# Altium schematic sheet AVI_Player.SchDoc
size A
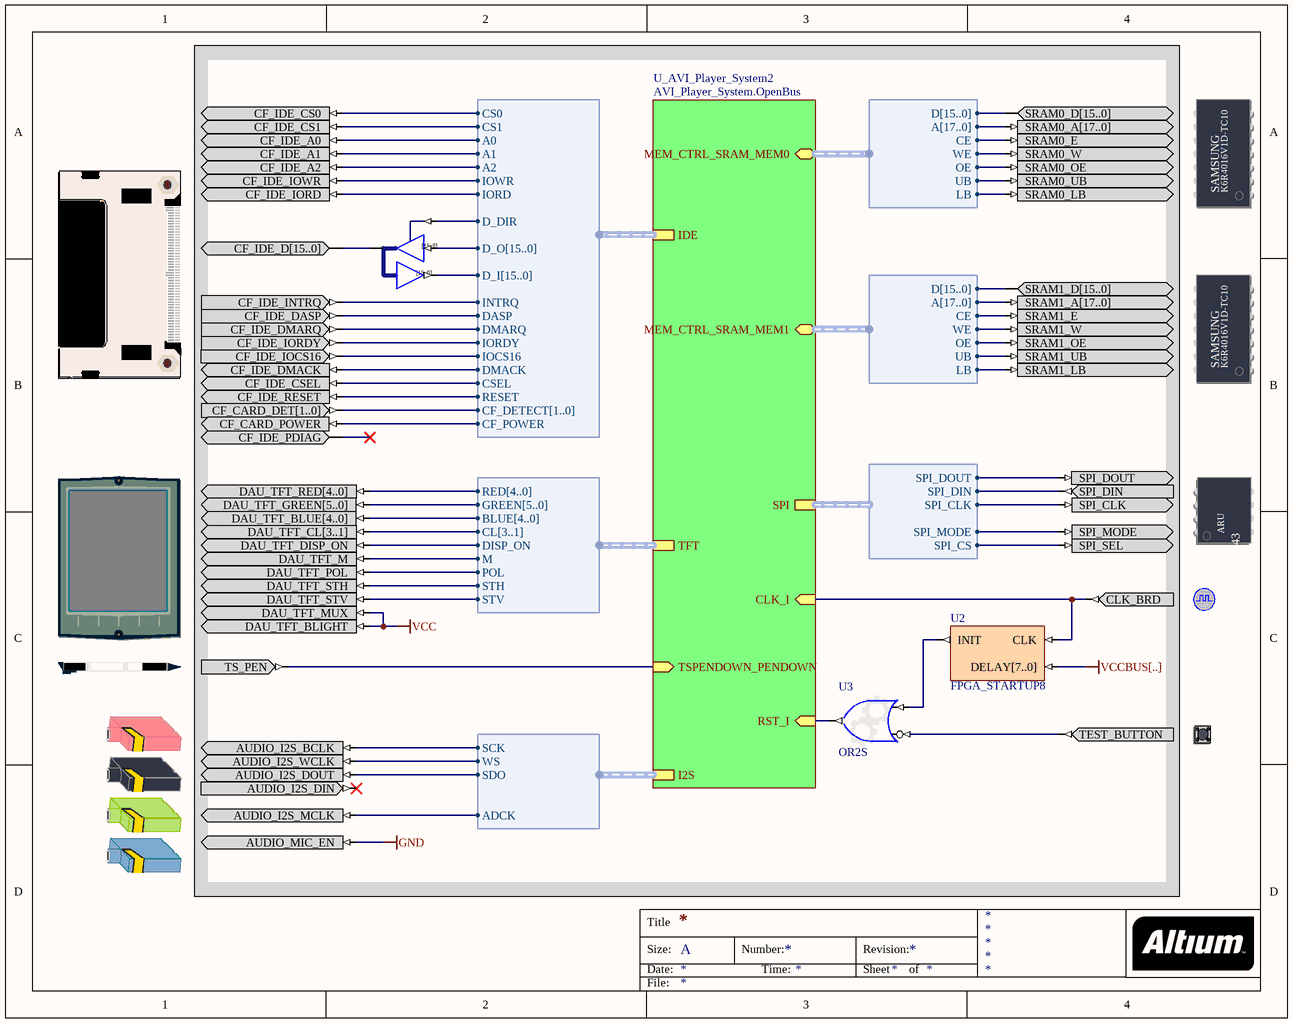
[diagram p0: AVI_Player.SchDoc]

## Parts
(Parts that share a designator on the sheet are numbered #1, #2 ... from top to bottom, then left to right.)
?#1  COMPACT_FLASH  (value not drawn)
?#2  SRAM_DAUGHTER0  (value not drawn)
?#3  SRAM_DAUGHTER1  (value not drawn)
?#4  TFT_LCD  (value not drawn)
?#5  TOUCH_SCREEN_DIGITIZER  (value not drawn)
?#6  CLOCK_BOARD  (value not drawn)
?#7  TOUCHSCREEN_PEN_DOWN  (value not drawn)
?#8  TEST_BUTTON  (value not drawn)
?#9  AUDIO_CODEC  (value not drawn)
U1  IOBUF16B  (value not drawn)
U2  FPGA_STARTUP8
U3  OR2S

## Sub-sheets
U_AVI_Player_System2 = AVI_Player_System.OpenBus: I2S (harness I2S_W_TX), SPI (harness SPI_W_NB), TSPENDOWN_PENDOWN (in), TFT (harness VGA32_TFT), IDE (harness WB_IDE), RST_I (in), CLK_I (in), MEM_CTRL_SRAM_MEM0 (harness WB_MEM_CTRL_SRAM16_A18), MEM_CTRL_SRAM_MEM1 (harness WB_MEM_CTRL_SRAM16_A18)

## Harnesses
WB_IDE: CS0, CS1, A0, A1, A2, IOWR, IORD, D_DIR, D_O[15..0], D_I[15..0], INTRQ, DASP, DMARQ, IORDY, IOCS16, DMACK, CSEL, RESET, CF_DETECT[1..0], CF_POWER
VGA32_TFT: RED[4..0], GREEN[5..0], BLUE[4..0], CL[3..1], DISP_ON, M, POL, STH, STV
SPI_W_NB: SPI_DOUT, SPI_DIN, SPI_CLK, SPI_MODE, SPI_CS
I2S_W_TX: SCK, WS, SDO, ADCK
WB_MEM_CTRL_SRAM16_A18: D[15..0], A[17..0], CE, WE, OE, UB, LB

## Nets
GND: ?#9.AUDIO_MIC_EN
VCC: ?#4.DAU_TFT_BLIGHT ?#4.DAU_TFT_MUX
Net?#1_CF_CARD_POWER: ?#1.CF_CARD_POWER ; sheet U_AVI_Player_System2/IDE.CF_POWER
Net?#1_CF_IDE_A0: ?#1.CF_IDE_A0 ; sheet U_AVI_Player_System2/IDE.A0
Net?#1_CF_IDE_A1: ?#1.CF_IDE_A1 ; sheet U_AVI_Player_System2/IDE.A1
Net?#1_CF_IDE_A2: ?#1.CF_IDE_A2 ; sheet U_AVI_Player_System2/IDE.A2
Net?#1_CF_IDE_CS0: ?#1.CF_IDE_CS0 ; sheet U_AVI_Player_System2/IDE.CS0
Net?#1_CF_IDE_CS1: ?#1.CF_IDE_CS1 ; sheet U_AVI_Player_System2/IDE.CS1
Net?#1_CF_IDE_CSEL: ?#1.CF_IDE_CSEL ; sheet U_AVI_Player_System2/IDE.CSEL
Net?#1_CF_IDE_DASP: ?#1.CF_IDE_DASP ; sheet U_AVI_Player_System2/IDE.DASP
Net?#1_CF_IDE_DMACK: ?#1.CF_IDE_DMACK ; sheet U_AVI_Player_System2/IDE.DMACK
Net?#1_CF_IDE_DMARQ: ?#1.CF_IDE_DMARQ ; sheet U_AVI_Player_System2/IDE.DMARQ
Net?#1_CF_IDE_INTRQ: ?#1.CF_IDE_INTRQ ; sheet U_AVI_Player_System2/IDE.INTRQ
Net?#1_CF_IDE_IOCS16: ?#1.CF_IDE_IOCS16 ; sheet U_AVI_Player_System2/IDE.IOCS16
Net?#1_CF_IDE_IORD: ?#1.CF_IDE_IORD ; sheet U_AVI_Player_System2/IDE.IORD
Net?#1_CF_IDE_IORDY: ?#1.CF_IDE_IORDY ; sheet U_AVI_Player_System2/IDE.IORDY
Net?#1_CF_IDE_IOWR: ?#1.CF_IDE_IOWR ; sheet U_AVI_Player_System2/IDE.IOWR
Net?#1_CF_IDE_RESET: ?#1.CF_IDE_RESET ; sheet U_AVI_Player_System2/IDE.RESET
Net?#2_SRAM0_E: ?#2.SRAM0_E ; sheet U_AVI_Player_System2/MEM_CTRL_SRAM_MEM0.CE
Net?#2_SRAM0_LB: ?#2.SRAM0_LB ; sheet U_AVI_Player_System2/MEM_CTRL_SRAM_MEM0.LB
Net?#2_SRAM0_OE: ?#2.SRAM0_OE ; sheet U_AVI_Player_System2/MEM_CTRL_SRAM_MEM0.OE
Net?#2_SRAM0_UB: ?#2.SRAM0_UB ; sheet U_AVI_Player_System2/MEM_CTRL_SRAM_MEM0.UB
Net?#2_SRAM0_W: ?#2.SRAM0_W ; sheet U_AVI_Player_System2/MEM_CTRL_SRAM_MEM0.WE
Net?#3_SRAM1_E: ?#3.SRAM1_E ; sheet U_AVI_Player_System2/MEM_CTRL_SRAM_MEM1.CE
Net?#3_SRAM1_LB: ?#3.SRAM1_LB ; sheet U_AVI_Player_System2/MEM_CTRL_SRAM_MEM1.LB
Net?#3_SRAM1_OE: ?#3.SRAM1_OE ; sheet U_AVI_Player_System2/MEM_CTRL_SRAM_MEM1.OE
Net?#3_SRAM1_UB: ?#3.SRAM1_UB ; sheet U_AVI_Player_System2/MEM_CTRL_SRAM_MEM1.UB
Net?#3_SRAM1_W: ?#3.SRAM1_W ; sheet U_AVI_Player_System2/MEM_CTRL_SRAM_MEM1.WE
Net?#4_DAU_TFT_DISP_ON: ?#4.DAU_TFT_DISP_ON ; sheet U_AVI_Player_System2/TFT.DISP_ON
Net?#4_DAU_TFT_M: ?#4.DAU_TFT_M ; sheet U_AVI_Player_System2/TFT.M
Net?#4_DAU_TFT_POL: ?#4.DAU_TFT_POL ; sheet U_AVI_Player_System2/TFT.POL
Net?#4_DAU_TFT_STH: ?#4.DAU_TFT_STH ; sheet U_AVI_Player_System2/TFT.STH
Net?#4_DAU_TFT_STV: ?#4.DAU_TFT_STV ; sheet U_AVI_Player_System2/TFT.STV
Net?#5_SPI_CLK: ?#5.SPI_CLK ; sheet U_AVI_Player_System2/SPI.SPI_CLK
Net?#5_SPI_DIN: ?#5.SPI_DIN ; sheet U_AVI_Player_System2/SPI.SPI_DIN
Net?#5_SPI_DOUT: ?#5.SPI_DOUT ; sheet U_AVI_Player_System2/SPI.SPI_DOUT
Net?#5_SPI_MODE: ?#5.SPI_MODE ; sheet U_AVI_Player_System2/SPI.SPI_MODE
Net?#5_SPI_SEL: ?#5.SPI_SEL ; sheet U_AVI_Player_System2/SPI.SPI_CS
Net?#6_CLK_BRD: ?#6.CLK_BRD U2.CLK ; sheet U_AVI_Player_System2/CLK_I
Net?#7_TS_PEN: ?#7.TS_PEN ; sheet U_AVI_Player_System2/TSPENDOWN_PENDOWN
Net?#8_TEST_BUTTON: ?#8.TEST_BUTTON U3.I1
Net?#9_AUDIO_I2S_BCLK: ?#9.AUDIO_I2S_BCLK ; sheet U_AVI_Player_System2/I2S.SCK
Net?#9_AUDIO_I2S_DOUT: ?#9.AUDIO_I2S_DOUT ; sheet U_AVI_Player_System2/I2S.SDO
Net?#9_AUDIO_I2S_MCLK: ?#9.AUDIO_I2S_MCLK ; sheet U_AVI_Player_System2/I2S.ADCK
Net?#9_AUDIO_I2S_WCLK: ?#9.AUDIO_I2S_WCLK ; sheet U_AVI_Player_System2/I2S.WS
NetU1_T: U1.T ; sheet U_AVI_Player_System2/IDE.D_DIR
NetU2_INIT: U2.INIT U3.I0
NetU3_O: U3.O ; sheet U_AVI_Player_System2/RST_I

Not connected (* = marked no-connect by the designer): ?#1 CF_CARD_DET[1..0] CF_IDE_D[15..0] CF_IDE_PDIAG*; ?#2 SRAM0_A[17..0] SRAM0_D[15..0]; ?#3 SRAM1_A[17..0] SRAM1_D[15..0]; ?#4 DAU_TFT_BLUE[4..0] DAU_TFT_CL[3..1] DAU_TFT_GREEN[5..0] DAU_TFT_RED[4..0]; ?#9 AUDIO_I2S_DIN*; U1 I[15..0] IO[15..0] O[15..0]; U2 DELAY[7..0]

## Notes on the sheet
- Labels drawn without touching a wire or pin: VCCBUS[..]

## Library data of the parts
?#1 = COMPACT_FLASH: Connector, Compact Flash Card Ejector 22mm; PortComponent: True
?#2 = SRAM_DAUGHTER0: Free Static RAM - Daughterboard; PortComponent: True
?#3 = SRAM_DAUGHTER1: Free Static RAM - Daughterboard; PortComponent: True
?#4 = TFT_LCD: TFT LCD Panel; PortComponent: True
?#5 = TOUCH_SCREEN_DIGITIZER: Touch Screen Digitizer; PortComponent: True
?#6 = CLOCK_BOARD: Global System Clock Supply; PortComponent: True
?#7 = TOUCH_SCREEN_PEN: TFT Touch Screen Pen; PortComponent: True
?#8 = TEST_BUTTON: Test / Reset Button; PortComponent: True
?#9 = AUDIO_CODEC: Audio Codec; PortComponent: True; IncludeInDSF: AUDIO_CS4270
U1 = IOBUF16B: 16-Bit Input/Output Buffer, Bus Version; SubClass: IOBUF; Enable: Low; Control: Common Control T; PortSize: 16; ArchiveName: GENERIC; VHDLIB_SIM: GENERIC_LIB
U2 = FPGA_STARTUP8: FPGA Startup With 8 Bit Delay
U3 = GATE: Configurable Generic Gate; ConfiguratorName: GENERIC_GATE; ConfigurationParameters: {}Version[1.1]{}GateKind[OR]{}BusInput[False]{}GateInputType[Bit]{}GateOutputOption[Normal]{}BusWidth[8]{}RegisterOutputs[False]{}NegativeClockEdge[False]{}InputCount[2]{}InputInvert0[False]{}InputInvert1[True]{}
